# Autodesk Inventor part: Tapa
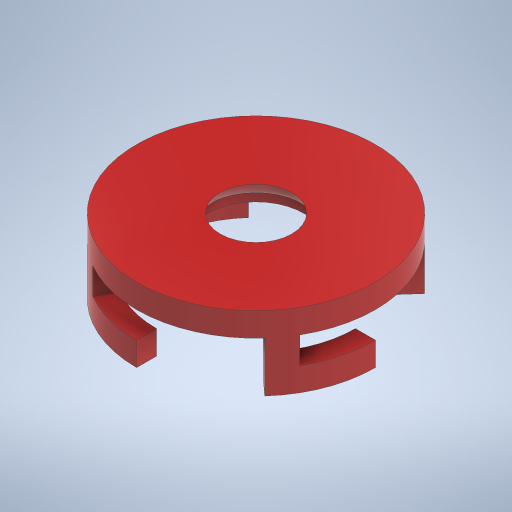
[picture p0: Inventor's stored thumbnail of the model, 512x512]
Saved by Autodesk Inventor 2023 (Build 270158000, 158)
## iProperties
Created: 2026-02
Part Number: Tapa
Material: Genérico
Document SubType Name: Modeling
Designer: JULIAN
Density: 1 g/cm^3
Appearance: Valor por defecto
Author: JULIAN
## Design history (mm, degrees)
sketch "Boceto1"
  geometry: C1 r 11 at (0, 0); C2 r 15 at (0, 0); 1 further point
  constraints: 2 centre point, 2 coincident
  dimensions: "d0" = 22 diameter of C1; "d1" = 30 diameter of C2
extrude "Extrusión1" new body sketch "Boceto1" distance "d2" = 3; taper "d3" = 0 deg
sketch "Boceto2"
  geometry: L1 (-12.5, 0)-(-15, 0); L2 (-9.289, 8.364)-(-11.147, 10.037); L3 (0, 0)-(15, 0); L4 (-10.825, 6.25)-(-12.99, 7.5); L5 (0, 0)-(15, 0); L6 (-8.364, -9.289)-(-10.037, -11.147); L7 (-6.25, -10.825)-(-7.5, -12.99); L8 (9.289, -8.364)-(11.147, -10.037); L9 (10.825, -6.25)-(12.99, -7.5); L10 (8.364, 9.289)-(10.037, 11.147); L11 (6.25, 10.825)-(7.5, 12.99); A1 r 12.5 centre (0, 0) between (-9.289, 8.364) and (-12.5, 0); A2 r 15 centre (0, 0) between (11.147, -10.037) and (15, 0); A3 r 15 centre (0, 0) between (-11.147, 10.037) and (-12.99, 7.5); A4 r 12.5 centre (0, 0) between (-8.364, -9.289) and (0, -12.5); A5 r 15 centre (0, 0) between (-10.037, -11.147) and (-7.5, -12.99); A6 r 12.5 centre (0, 0) between (9.289, -8.364) and (12.5, 0); A7 r 15 centre (0, 0) between (11.147, -10.037) and (12.99, -7.5); A8 r 12.5 centre (0, 0) between (8.364, 9.289) and (0, 12.5); A9 r 15 centre (0, 0) between (10.037, 11.147) and (7.5, 12.99); 6 further points
  constraints: 22 end point, 22 point on circle, 9 centre point, 5 coincident, 4 point on line, 3 horizontal, 49 other
  dimensions: "d5" = 138 deg angle of L3 L2; "d6" = 150 deg angle of L5 L4; "d9" = 360 deg dimension on point (0, 0) L2.start (derived)
extrude "Extrusión2" join sketch "Boceto2" distance "d11" = 6.3; taper "d12" = 0 deg
sketch "Boceto3"
  geometry: L1 (-7.5, 12.99)-(-6.25, 10.825) reference; L2 (11.147, 10.037)-(9.289, 8.364) reference; L3 (9.289, 8.364)-(11.147, 10.037); L4 (12.5, 0)-(15, 0); L5 (0, 12.5)-(0, 15); L6 (-8.364, 9.289)-(-10.037, 11.147); L7 (-12.5, 0)-(-15, 0); L8 (-9.289, -8.364)-(-11.147, -10.037); L9 (0, -12.5)-(0, -15); L10 (8.364, -9.289)-(10.037, -11.147); A1 r 12.5 centre (0, 0) between (9.289, 8.364) and (-6.25, 10.825) reference; A2 r 12.5 centre (0, 0) between (12.5, 0) and (9.289, 8.364); A3 r 15 centre (0, 0) between (15, 0) and (11.147, 10.037); A4 r 12.5 centre (0, 0) between (0, 12.5) and (-8.364, 9.289); A5 r 15 centre (0, 0) between (0, 15) and (-10.037, 11.147); A6 r 12.5 centre (0, 0) between (-12.5, 0) and (-9.289, -8.364); A7 r 15 centre (0, 0) between (-15, 0) and (-11.147, -10.037); A8 r 12.5 centre (0, 0) between (0, -12.5) and (8.364, -9.289); A9 r 15 centre (0, 0) between (0, -15) and (10.037, -11.147); 3 further points
  constraints: 18 end point, 16 point on circle, 8 centre point, 5 coincident, 5 point on line, 1 collinear, 1 horizontal, 45 other
  dimensions: "d15" = 360 deg dimension on point (0, 0) L4.start (derived)
extrude "Extrusión3" join sketch "Boceto3" distance "d17" = 3; taper "d18" = 0 deg
sketch "Boceto4"
  geometry: L1 (0, 0)-(6, 0); L2 (7.5, 0)-(-11.147, 0) reference; L3 (0, 0)-(6, 0); L4 (-11, 3)-(11, 3) reference; L5 (0, 3)-(4.5, 3); L6 (0, 3)-(4.5, 3); L7 (6, 0)-(6, 1); L8 (4.5, 3)-(15, 3); L9 (15, -6.3)-(15, 3) reference; L10 (15, 0)-(15, 3); L11 (15, 0)-(6, 0); L12 (0, -8.479)-(0, 6.772) reference; A1 r 4.5 centre (8.708, 4.594) between (4.5, 3) and (6, 1); 4 further points
  constraints: 16 end point, 4 collinear, 3 horizontal, 2 perpendicular, 2 point on circle, 2 point on line, 1 centre point, 1 midpoint, 1 vertical
  dimensions: "d19" = 6 distance of L1.start L1.end; "d20" = 0 distance between parallel lines of L1 L3 (derived); "d21" = 4.5 distance of L5.start L5.end; "d22" = 0 distance between parallel lines of L5 L6 (derived); "d23" = 1 distance of L3.end L7.end; "d24" = 4.5 radius of A1
revolve "Revolución1" sketch "Boceto4" stored, may be unused: angle "d25" = 90 deg
node "Sólido1"
